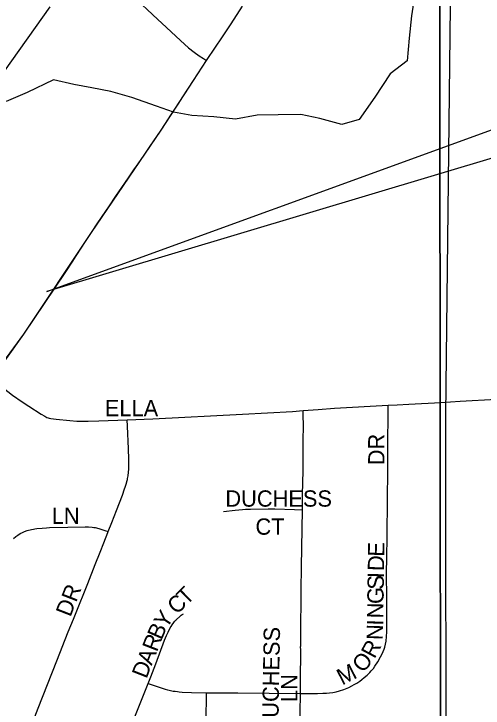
# Model space of a CAD drawing. Extents: x 0 to 34, y 0 to 22.
# Drawn here: x 5.3403 to 5.4766, y 18.1359 to 18.3375 of the extents above; entities that cross this region are included whole.
import ezdxf

# ---------------------------------------------------------------- set-up
doc = ezdxf.new("R2010")
doc.units = 0
for name, color, linetype in [('Default', 7, 'Continuous'), ('GM_X_City_Street', 7, 'Continuous'), ('GM_X_City_Street_Text', 7, 'Continuous'), ('GM_X_Corporation', 7, 'Continuous'), ('GM_X_Minor_River', 7, 'Continuous'), ('GM_X_Section', 7, 'Continuous'), ('GM_X_State_Route', 7, 'Continuous'), ('GM_X_Township', 7, 'Continuous'), ('SH_Text', 7, 'Continuous')]:
    doc.layers.add(name, color=color, linetype=linetype)

msp = doc.modelspace()

# ---------------------------------------------------------------- linework, layer by layer
at = {"layer": 'Default'}
msp.add_lwpolyline([(5.32122, 18.21295), (5.33402, 18.2318), (5.34318, 18.24455), (5.36283, 18.27403), (5.38306, 18.30374), (5.39246, 18.31816)], dxfattribs=at)
at = {"layer": 'GM_X_City_Street'}
for points in [[(5.34401, 18.37254), (5.34464, 18.37196), (5.34532, 18.37133), (5.34797, 18.36876), (5.34908, 18.3677), (5.3502, 18.36663), (5.35199, 18.36491), (5.35663, 18.36036), (5.36172, 18.35538), (5.36822, 18.34915), (5.37226, 18.3453), (5.37449, 18.34313), (5.38214, 18.33587), (5.38327, 18.33481), (5.38735, 18.33103), (5.38872, 18.32979), (5.39099, 18.32771), (5.39266, 18.32638), (5.39411, 18.32534), (5.39537, 18.32459), (5.39631, 18.32403)], [(5.33402, 18.2318), (5.33517, 18.23063), (5.33624, 18.22966), (5.33993, 18.22681), (5.34275, 18.22487), (5.34468, 18.22363), (5.34826, 18.22131), (5.34929, 18.22068), (5.34964, 18.2205), (5.34993, 18.22037), (5.35025, 18.22025), (5.35053, 18.22015), (5.35107, 18.22002), (5.35262, 18.21983), (5.35655, 18.21944), (5.35859, 18.2193), (5.36022, 18.21924), (5.36175, 18.21926)], [(5.44904, 18.22389), (5.45161, 18.22402), (5.45503, 18.22416), (5.46434, 18.22473), (5.46992, 18.22503), (5.48046, 18.22569), (5.48945, 18.22633), (5.4947, 18.22678), (5.50059, 18.22726), (5.50863, 18.22787), (5.51544, 18.22838), (5.5241, 18.2291)], [(5.42352, 18.14019), (5.42845, 18.1402), (5.43001, 18.14024), (5.43111, 18.14027), (5.43201, 18.14034), (5.43297, 18.14046), (5.43389, 18.14066), (5.43488, 18.14093), (5.4361, 18.14136), (5.43757, 18.14197), (5.43843, 18.14239), (5.43914, 18.14276), (5.4399, 18.1432), (5.44074, 18.14377), (5.44139, 18.14424), (5.44209, 18.1448), (5.44289, 18.14552), (5.44365, 18.14631), (5.44411, 18.1468), (5.44471, 18.14746), (5.44518, 18.14811), (5.446, 18.1494), (5.44682, 18.15083), (5.44718, 18.15152), (5.4476, 18.15239), (5.44789, 18.1531), (5.44805, 18.1536), (5.44826, 18.1545), (5.44842, 18.15542), (5.44856, 18.15671), (5.44864, 18.15809), (5.44865, 18.1597), (5.4486, 18.16287), (5.44859, 18.16787), (5.44858, 18.16942), (5.4486, 18.17035), (5.44857, 18.17252), (5.44857, 18.175), (5.44864, 18.17981), (5.44874, 18.18558), (5.44886, 18.19677), (5.44889, 18.20451), (5.4489, 18.20761), (5.44893, 18.21211), (5.44902, 18.22197), (5.44904, 18.22389)], [(5.42432, 18.22232), (5.42871, 18.2227), (5.4334, 18.22303), (5.44904, 18.22389)], [(5.37327, 18.21961), (5.38072, 18.21998), (5.40667, 18.22129), (5.42125, 18.22212), (5.42432, 18.22232)], [(5.4241, 18.19356), (5.42417, 18.19783), (5.42431, 18.20497), (5.42435, 18.21416), (5.4244, 18.21745), (5.42441, 18.21859), (5.42438, 18.22039), (5.42434, 18.22166), (5.42432, 18.22232)], [(5.36175, 18.21926), (5.3619, 18.21927), (5.36504, 18.21935), (5.37327, 18.21961)], [(5.36774, 18.18718), (5.36877, 18.18989), (5.37014, 18.19332), (5.37183, 18.19778), (5.37246, 18.19957), (5.37263, 18.20009), (5.37289, 18.20098), (5.37319, 18.20199), (5.37328, 18.20231), (5.37334, 18.20258), (5.37342, 18.20296), (5.3735, 18.20343), (5.37361, 18.20442), (5.37367, 18.20533), (5.3737, 18.20608), (5.37372, 18.2075), (5.37371, 18.20828), (5.37361, 18.21119), (5.37337, 18.21778), (5.37327, 18.21961)], [(5.40121, 18.19303), (5.40458, 18.19338), (5.40673, 18.1936), (5.40755, 18.19367), (5.40819, 18.19371), (5.40903, 18.19374), (5.41421, 18.19379), (5.4161, 18.19378), (5.42185, 18.19363), (5.4241, 18.19356)], [(5.42352, 18.14019), (5.42355, 18.14581), (5.42364, 18.15072), (5.42361, 18.15288), (5.4236, 18.15377), (5.42363, 18.15403), (5.42368, 18.15494), (5.42369, 18.15679), (5.42368, 18.16115), (5.42374, 18.1658), (5.42376, 18.17016), (5.42386, 18.177), (5.4241, 18.19356)], [(5.3402, 18.18518), (5.34086, 18.18574), (5.34148, 18.18621), (5.34217, 18.18663), (5.3428, 18.18696), (5.34346, 18.18725), (5.34418, 18.18749), (5.3454, 18.18782), (5.34603, 18.18795), (5.34643, 18.18801), (5.34702, 18.18808), (5.34857, 18.18823), (5.34982, 18.18832), (5.35069, 18.18835), (5.35596, 18.18846), (5.361, 18.18856), (5.36202, 18.18854), (5.36303, 18.18847), (5.36352, 18.18842), (5.36389, 18.18836), (5.36503, 18.18809), (5.3659, 18.18782), (5.36706, 18.18741), (5.36774, 18.18718)], [(5.31491, 18.05412), (5.31665, 18.05852), (5.31797, 18.06171), (5.31914, 18.06468), (5.32043, 18.06789), (5.32343, 18.0757), (5.32836, 18.08845), (5.33197, 18.09772), (5.33671, 18.1092), (5.33919, 18.11542), (5.34093, 18.11983), (5.34511, 18.13007), (5.34742, 18.13595), (5.35285, 18.14963), (5.35611, 18.15806), (5.3576, 18.16181), (5.35936, 18.16612), (5.36064, 18.16926), (5.36179, 18.1721), (5.36393, 18.17761), (5.36543, 18.18125), (5.36649, 18.18391), (5.36766, 18.18698), (5.36774, 18.18718)], [(5.37934, 18.14306), (5.3801, 18.14505), (5.38156, 18.14876), (5.38411, 18.15564), (5.38466, 18.15701), (5.3851, 18.15803), (5.3857, 18.15923), (5.38596, 18.15965), (5.38626, 18.16012), (5.38673, 18.16078), (5.38696, 18.16107), (5.38711, 18.16125), (5.38731, 18.16145), (5.38757, 18.16171), (5.38851, 18.16255), (5.38865, 18.16267), (5.3888, 18.1628), (5.38894, 18.1629), (5.38924, 18.16312), (5.38963, 18.16336)], [(5.36805, 18.11497), (5.37684, 18.13684), (5.37934, 18.14306)], [(5.37934, 18.14306), (5.38426, 18.14143), (5.38496, 18.14124), (5.38544, 18.14113), (5.3858, 18.14105), (5.38661, 18.1409), (5.38718, 18.14082), (5.38782, 18.14074), (5.38833, 18.14067), (5.38915, 18.14058), (5.39192, 18.14043), (5.3963, 18.14037)], [(5.39618, 18.13263), (5.39629, 18.13982), (5.3963, 18.14037)], [(5.3963, 18.14037), (5.40533, 18.14033), (5.42352, 18.14019)], [(5.42355, 18.12392), (5.42354, 18.12596), (5.42354, 18.12875), (5.42349, 18.13461), (5.42352, 18.14019)]]:
    msp.add_lwpolyline(points, dxfattribs=at)
at = {"layer": 'GM_X_Corporation'}
msp.add_lwpolyline([(5.33764, 18.3209), (5.35084, 18.33959)], dxfattribs=at)
at = {"layer": 'GM_X_Minor_River'}
msp.add_lwpolyline([(5.45675, 18.34341), (5.45575, 18.33696), (5.45514, 18.33052), (5.45452, 18.32388), (5.44956, 18.32012), (5.44515, 18.31333), (5.44055, 18.30691), (5.4356, 18.30543), (5.42917, 18.30719), (5.42367, 18.30837), (5.41703, 18.30823), (5.41096, 18.30809), (5.40469, 18.307), (5.39843, 18.30761), (5.39198, 18.30804), (5.38668, 18.30903), (5.38176, 18.31078), (5.37457, 18.3133), (5.36851, 18.31505), (5.36301, 18.31604), (5.35771, 18.31703), (5.35184, 18.3184), (5.34422, 18.31467), (5.33813, 18.31206)], dxfattribs=at)
at = {"layer": 'GM_X_Section'}
for points in [[(5.46396, 18.4161), (5.4644, 17.92291), (5.46435, 17.9159), (4.95614, 17.90875), (4.95692, 18.41406), (5.46379, 18.41876)], [(5.99052, 18.41894), (5.98372, 17.92012), (5.4644, 17.92291), (5.46396, 18.4161)]]:
    msp.add_lwpolyline(points, close=True, dxfattribs=at)
at = {"layer": 'GM_X_State_Route'}
for points in [[(5.39246, 18.31816), (5.39631, 18.32403), (5.39645, 18.32425), (5.40093, 18.33083), (5.40344, 18.33469), (5.40675, 18.33979)], [(5.33632, 18.23512), (5.34318, 18.24455), (5.35523, 18.26232), (5.35742, 18.26571), (5.35841, 18.26729), (5.36112, 18.27145), (5.36283, 18.27403), (5.36456, 18.27661), (5.36595, 18.27866), (5.36787, 18.28149), (5.36996, 18.28457), (5.3717, 18.28714), (5.37363, 18.28995), (5.37536, 18.29251), (5.37572, 18.29301), (5.37817, 18.29656), (5.37975, 18.29885), (5.38099, 18.30064), (5.38306, 18.30374), (5.38613, 18.30842), (5.38748, 18.3105), (5.388, 18.31128), (5.38936, 18.31344), (5.39246, 18.31816)]]:
    msp.add_lwpolyline(points, dxfattribs=at)
at = {"layer": 'GM_X_Township'}
for points in [[(4.32513, 17.40324), (4.77846, 17.40425), (4.99421, 17.40763), (5.46352, 17.41199), (5.46485, 17.53523), (5.46518, 17.63837), (5.46592, 17.82417), (5.46606, 17.86097), (5.46575, 18.22108), (5.4678, 18.39922), (5.46813, 18.42722), (5.46918, 18.51868), (5.46955, 18.55069), (5.47024, 18.61055), (5.47055, 18.63752), (5.47095, 18.67198), (5.47122, 18.69589), (5.47192, 18.75628), (5.47212, 18.77357), (5.47293, 18.84412), (5.47565, 19.08008)], [(6.97838, 17.41123), (6.85112, 17.41144), (6.74587, 17.41079), (6.41604, 17.41268), (6.21985, 17.41235), (5.85482, 17.41232), (5.46352, 17.41199), (5.46485, 17.53523), (5.46518, 17.63837), (5.46592, 17.82417), (5.46606, 17.86097), (5.46575, 18.22108), (5.4678, 18.39922), (5.46813, 18.42722), (5.46918, 18.51868), (5.46955, 18.55069), (5.47024, 18.61055), (5.47055, 18.63752), (5.47095, 18.67198), (5.47122, 18.69589), (5.47192, 18.75628), (5.47212, 18.77357), (5.47293, 18.84412), (5.47565, 19.08008)]]:
    msp.add_lwpolyline(points, dxfattribs=at)
at = {"layer": 'SH_Text'}
msp.add_lwpolyline([(9.91391, 19.62604), (5.3499, 18.25689), (9.91668, 19.92045)], close=True, dxfattribs=at)

# ---------------------------------------------------------------- texts
at = {"layer": 'GM_X_City_Street_Text'}
for s, height, rotation, p in [('ELLA', 0.004735, 0, (5.36674, 18.22069)), ('DR', 0.004735, 90, (5.44794, 18.20646)), ('DUCHESS', 0.004735, 0, (5.40174, 18.19444)), ('LN', 0.004735, 0, (5.35133, 18.18944)), ('CT', 0.004735, 0, (5.41049, 18.18629)), ('E', 0.00473, 89.1412, (5.44787, 18.17989)), ('D', 0.00473, 89.1038, (5.44781, 18.17572)), ('I', 0.00473, 89.126, (5.44778, 18.17364)), ('S', 0.00473, 89.1257, (5.44773, 18.1703)), ('DR', 0.004735, 68.7471, (5.35675, 18.1622)), ('T', 0.00473, 44.8524, (5.39044, 18.1656)), ('G', 0.00473, 89.1144, (5.44766, 18.16614)), ('C', 0.00473, 42.6806, (5.38754, 18.16292)), ('Y', 0.00473, 56.3705, (5.38461, 18.15873)), ('N', 0.00473, 89.1144, (5.4476, 18.16197)), ('B', 0.00473, 66.0745, (5.38319, 18.15549)), ('I', 0.00473, 88.8286, (5.44755, 18.15987)), ('DUCHESS', 0.004735, 89.0167, (5.4171, 18.12853)), ('N', 0.00473, 88.394, (5.44744, 18.15566)), ('R', 0.00473, 68.7306, (5.38185, 18.15205)), ('R', 0.00473, 61.9908, (5.44507, 18.15007)), ('A', 0.00473, 68.7445, (5.38034, 18.14817)), ('O', 0.00473, 48.6683, (5.44164, 18.14595)), ('D', 0.00473, 68.7302, (5.37883, 18.14428)), ('M', 0.00473, 26.956, (5.43564, 18.14249)), ('LN', 0.004735, 90, (5.42266, 18.13771))]:
    msp.add_text(s, height=height, rotation=rotation, dxfattribs=at).set_placement(p)

doc.saveas('drawing.dxf')
